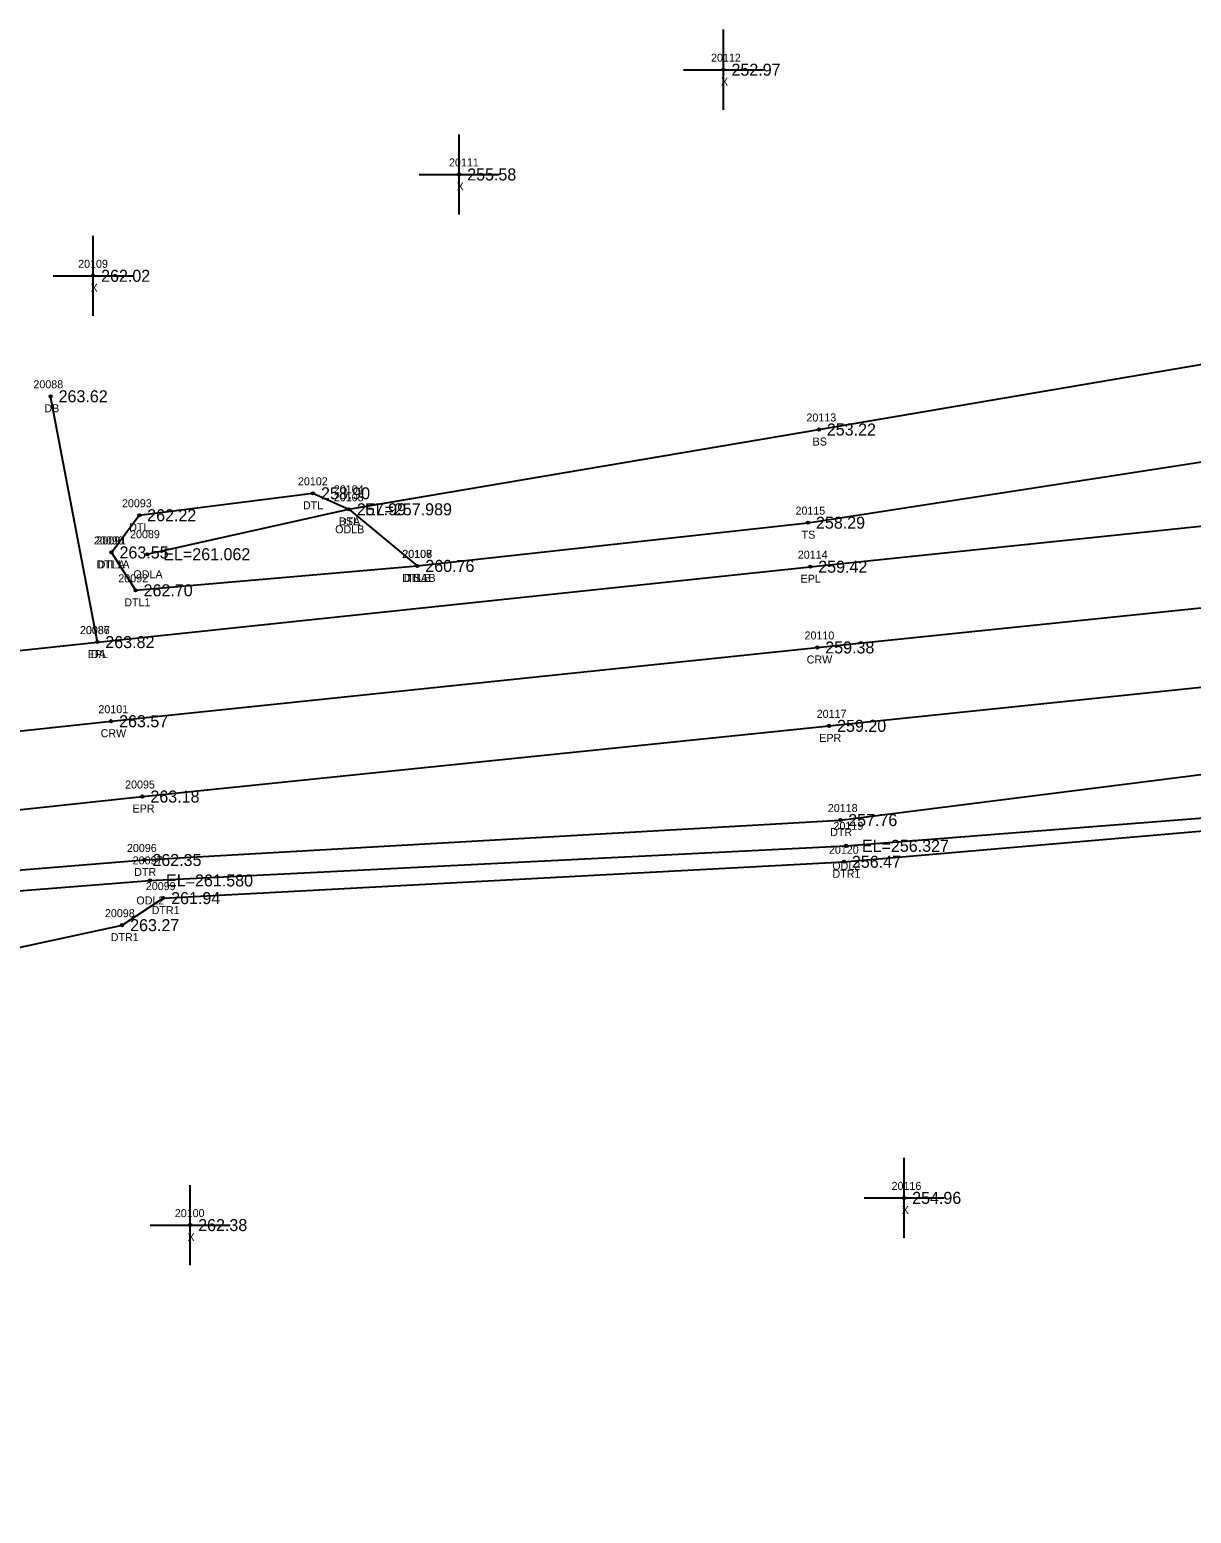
# Model space of a CAD drawing. Extents: x 2275563 to 2277161, y 1075719 to 1076412.
# Drawn here: x 2275956.7 to 2276101.9, y 1075932.2 to 1076117.6 of the extents above; entities that cross this region are included whole.
import ezdxf

# ---------------------------------------------------------------- set-up
doc = ezdxf.new("R2010")
doc.units = 0
for name, color, linetype in [('RD_DTM_BkLn1', 7, 'Continuous'), ('RD_DTM_BkLn2', 7, 'Continuous'), ('RD_DTM_BkLn_txCode', 7, 'Continuous'), ('RD_EX_Driveway', 7, 'Continuous'), ('RD_EX_Driveway_txCode', 7, 'Continuous'), ('RD_EX_H2O', 7, 'Continuous'), ('RD_EX_H2O_txCode', 7, 'Continuous'), ('RD_EX_Misc', 7, 'Continuous'), ('RD_EX_Misc_txCode', 7, 'Continuous'), ('RD_EX_Road', 7, 'Continuous'), ('RD_EX_Road_txCode', 7, 'Continuous'), ('RD_EX_TX_Driveway_ELEV', 7, 'Continuous'), ('RD_EX_TX_H2O_ELEV', 7, 'Continuous'), ('RD_EX_TX_Misc_ELEV', 7, 'Continuous'), ('RD_EX_TX_Road_ELEV', 7, 'Continuous'), ('RD_HC_Survey_ELEV', 7, 'Continuous'), ('RD_HC_Survey_txCode', 7, 'Continuous'), ('RD_SMD_Locator', 7, 'Continuous')]:
    doc.layers.add(name, color=color, linetype=linetype)

msp = doc.modelspace()

# ---------------------------------------------------------------- linework, layer by layer
at = {"layer": 'RD_DTM_BkLn1'}
msp.add_lwpolyline([(2275581.11, 1075960.98), (2275628.56, 1075975.85), (2275676.42, 1075988.42), (2275723.3, 1075998.64), (2275773.11, 1076007.87), (2275820.75, 1076014.85), (2275866.6, 1076020.4), (2275966.91, 1076031.19), (2276055.16, 1076040.4), (2276149.88, 1076050.18), (2276235.38, 1076058.41), (2276319.71, 1076067.21)], dxfattribs=at)
at = {"layer": 'RD_DTM_BkLn2'}
for points in [[(2275996.63, 1076057.66), (2276055.36, 1076067.63), (2276157.86, 1076085.08), (2276161.29, 1076085.91), (2276230.76, 1076096.53), (2276259.06, 1076089.7), (2276286.01, 1076102.67), (2276316.19, 1076099.9), (2276328.57, 1076094.65)], [(2276005.18, 1076050.59), (2276054, 1076055.99), (2276147.58, 1076070.47), (2276233.91, 1076079.18), (2276270.23, 1076080.23), (2276308.93, 1076086.72), (2276316.33, 1076084.42), (2276319.11, 1076080.29)]]:
    msp.add_lwpolyline(points, dxfattribs=at)
at = {"layer": 'RD_EX_Driveway'}
msp.add_line((2275965.19, 1076041.07), (2275959.35, 1076071.78), dxfattribs=at)
at = {"layer": 'RD_EX_H2O'}
msp.add_line((2275971.43, 1076052.05), (2275996.63, 1076057.66), dxfattribs=at)
for points in [[(2275966.96, 1076052.27), (2275970.42, 1076056.92), (2275992.14, 1076059.66), (2275996.63, 1076057.66), (2276005.18, 1076050.59)], [(2275966.96, 1076052.27), (2275969.97, 1076047.54), (2276005.18, 1076050.59)], [(2275584.42, 1075945.55), (2275630.75, 1075959.99), (2275679.72, 1075972.8), (2275727.1, 1075983.01), (2275776.52, 1075992.46), (2275822.09, 1075998.61), (2275868.31, 1076005.5), (2275971.07, 1076013.85), (2276058.03, 1076018.84), (2276110, 1076025.4), (2276114.25, 1076022.31), (2276152.59, 1076021.64), (2276188.46, 1076022.22), (2276200.36, 1076021.35), (2276207.63, 1076015.4), (2276245.53, 1076014.24), (2276263.41, 1076017.81), (2276276.57, 1076007.97), (2276280.95, 1075989.03), (2276329.97, 1075967.39)], [(2275584.66, 1075942.4), (2275631.99, 1075956.6), (2275680.23, 1075970.55), (2275727.34, 1075980.71), (2275776.9, 1075989.93), (2275822.49, 1075996.83), (2275868.2, 1076003.14), (2275971.77, 1076011.3), (2276058.74, 1076015.62), (2276117.31, 1076020.2), (2276152.71, 1076018.31), (2276188.2, 1076020.3), (2276200.59, 1076018.25), (2276207.46, 1076011.88), (2276246.17, 1076010.02), (2276264.15, 1076012.48), (2276274.37, 1076006.56), (2276276.43, 1075986.9), (2276334.04, 1075961.68)], [(2275587.87, 1075932.23), (2275632.3, 1075945.74), (2275680.34, 1075962.3), (2275730.43, 1075971.98), (2275777.84, 1075981.49), (2275823.91, 1075987.34), (2275869.26, 1075992.75), (2275941.88, 1076000), (2275968.29, 1076005.71), (2275973.41, 1076009.09), (2276058.49, 1076013.63), (2276114.54, 1076018.47), (2276125.61, 1076012.99), (2276153.29, 1076014.06), (2276186.69, 1076017.67), (2276196.76, 1076016.05), (2276210.13, 1076008.45), (2276246.2, 1076005.42), (2276264.34, 1076010.6), (2276271.38, 1076006), (2276275.05, 1075983.37), (2276331.39, 1075956.06)]]:
    msp.add_lwpolyline(points, dxfattribs=at)
at = {"layer": 'RD_EX_Misc'}
for p, q in [((2276043.44, 1076107.58), (2276043.44, 1076117.58)), ((2276038.44, 1076112.58), (2276048.44, 1076112.58)), ((2276010.41, 1076094.49), (2276010.41, 1076104.49)), ((2276005.41, 1076099.49), (2276015.41, 1076099.49)), ((2275964.66, 1076081.83), (2275964.66, 1076091.83)), ((2275959.66, 1076086.83), (2275969.66, 1076086.83)), ((2276066.02, 1075966.64), (2276066.02, 1075976.64)), ((2275976.79, 1075963.24), (2275976.79, 1075973.24)), ((2276061.02, 1075971.64), (2276071.02, 1075971.64)), ((2275971.79, 1075968.24), (2275981.79, 1075968.24))]:
    msp.add_line(p, q, dxfattribs=at)
at = {"layer": 'RD_EX_Road'}
for points in [[(2275577.73, 1075970.55), (2275625.95, 1075985.49), (2275674.01, 1075998.04), (2275722.5, 1076008.98), (2275771.65, 1076017.82), (2275820.48, 1076025.1), (2275865.7, 1076030.61), (2275949.17, 1076039.36), (2275965.19, 1076041.07), (2276054.28, 1076050.49), (2276149.42, 1076060.39), (2276235.13, 1076068.68), (2276318.87, 1076076.96)], [(2275583.24, 1075951.04), (2275629.66, 1075965.93), (2275678.06, 1075978.68), (2275725.56, 1075989.06), (2275775.66, 1075998.23), (2275820.79, 1076005.15), (2275867.87, 1076010.76), (2275970.82, 1076021.78), (2276056.64, 1076030.61), (2276150.8, 1076040.39), (2276237.04, 1076048.76), (2276320.71, 1076057.95)]]:
    msp.add_lwpolyline(points, dxfattribs=at)
at = {"layer": 'RD_SMD_Locator'}
for centre in [(2276043.44, 1076112.58), (2276010.41, 1076099.49), (2275964.66, 1076086.83), (2275959.35, 1076071.78), (2276055.36, 1076067.63), (2275992.14, 1076059.66), (2275970.42, 1076056.92), (2275996.63, 1076057.66), (2275996.63, 1076057.66), (2275996.63, 1076057.66), (2276054, 1076055.99), (2275966.96, 1076052.27), (2275966.96, 1076052.27), (2275971.43, 1076052.05), (2276005.18, 1076050.59), (2276005.18, 1076050.59), (2276005.18, 1076050.59), (2276054.28, 1076050.49), (2275969.97, 1076047.54), (2275965.19, 1076041.07), (2275965.19, 1076041.07), (2276055.16, 1076040.4), (2275966.91, 1076031.19), (2276056.64, 1076030.61), (2275970.82, 1076021.78), (2276058.03, 1076018.84), (2276058.74, 1076015.62), (2275971.07, 1076013.85), (2276058.49, 1076013.63), (2275971.77, 1076011.3), (2275973.41, 1076009.09), (2275968.29, 1076005.71), (2276066.02, 1075971.64), (2275976.79, 1075968.24)]:
    msp.add_circle(centre, 0.15, dxfattribs=at)

# ---------------------------------------------------------------- texts
at = {"layer": 'RD_DTM_BkLn_txCode'}
for s, p in [('20113', (2276053.81, 1076068.63)), ('BS', (2276054.58, 1076065.63)), ('20105', (2275994.75, 1076058.66)), ('BSA', (2275995.36, 1076055.66)), ('20115', (2276052.44, 1076056.99)), ('TS', (2276053.2, 1076053.99)), ('20108', (2276003.31, 1076051.59)), ('TSA', (2276003.9, 1076048.59))]:
    msp.add_text(s, height=1, dxfattribs=at).set_placement(p)
at = {"layer": 'RD_EX_Driveway_txCode'}
for s, p in [('20088', (2275957.2, 1076072.78)), ('DB', (2275958.57, 1076069.78)), ('20087', (2275963.03, 1076042.07)), ('DA', (2275964.39, 1076039.07))]:
    msp.add_text(s, height=1, dxfattribs=at).set_placement(p)
at = {"layer": 'RD_EX_H2O_txCode'}
for s, p in [('20102', (2275990.26, 1076060.66)), ('20104', (2275994.75, 1076059.66)), ('20093', (2275968.27, 1076057.92)), ('DTL', (2275990.89, 1076057.66)), ('20103', (2275994.75, 1076058.66)), ('DTL', (2275995.38, 1076055.66)), ('DTL', (2275969.18, 1076054.92)), ('20089', (2275969.28, 1076054.05)), ('ODLB', (2275994.91, 1076054.66)), ('20090', (2275964.76, 1076053.27)), ('20091', (2275965.08, 1076053.27)), ('20106', (2276003.29, 1076051.59)), ('20107', (2276003.31, 1076051.59)), ('DTL1A', (2275965.06, 1076050.27)), ('DTLA', (2275965.23, 1076050.27)), ('20092', (2275967.81, 1076048.54)), ('ODLA', (2275969.7, 1076049.05)), ('DTL1B', (2276003.3, 1076048.59)), ('DTLB', (2276003.47, 1076048.59)), ('DTL1', (2275968.56, 1076045.54)), ('20118', (2276056.48, 1076019.84)), ('DTR', (2276056.77, 1076016.84)), ('20119', (2276057.19, 1076017.62)), ('20096', (2275968.89, 1076014.85)), ('20120', (2276056.62, 1076014.63)), ('20097', (2275969.61, 1076013.3)), ('ODL2', (2276057.04, 1076012.62)), ('DTR', (2275969.8, 1076011.85)), ('DTR1', (2276057.06, 1076011.63)), ('20099', (2275971.25, 1076010.09)), ('ODL2', (2275970.07, 1076008.3)), ('DTR1', (2275971.98, 1076007.09)), ('20098', (2275966.14, 1076006.71)), ('DTR1', (2275966.86, 1076003.71))]:
    msp.add_text(s, height=1, dxfattribs=at).set_placement(p)
at = {"layer": 'RD_EX_Misc_txCode'}
for s, p in [('20112', (2276041.89, 1076113.58)), ('X', (2276043.13, 1076110.58)), ('20111', (2276009.14, 1076100.49)), ('X', (2276010.1, 1076097.49)), ('20109', (2275962.79, 1076087.83)), ('X', (2275964.35, 1076084.83)), ('20116', (2276064.45, 1075972.64)), ('20100', (2275974.87, 1075969.24)), ('X', (2276065.71, 1075969.64)), ('X', (2275976.47, 1075966.24))]:
    msp.add_text(s, height=1, dxfattribs=at).set_placement(p)
at = {"layer": 'RD_EX_Road_txCode'}
for s, p in [('20114', (2276052.73, 1076051.49)), ('EPL', (2276053.08, 1076048.49)), ('20086', (2275963.01, 1076042.07)), ('EPL', (2275963.98, 1076039.07)), ('20117', (2276055.09, 1076031.61)), ('EPR', (2276055.41, 1076028.61)), ('20095', (2275968.66, 1076022.78)), ('EPR', (2275969.59, 1076019.78))]:
    msp.add_text(s, height=1, dxfattribs=at).set_placement(p)
at = {"layer": 'RD_EX_TX_Driveway_ELEV'}
for s, p in [('263.62', (2275960.35, 1076071.03)), ('263.82', (2275966.19, 1076040.32))]:
    msp.add_text(s, height=1.5, dxfattribs=at).set_placement(p)
at = {"layer": 'RD_EX_TX_H2O_ELEV'}
for s, p in [('258.90', (2275993.14, 1076058.91)), ('257.99', (2275997.63, 1076056.91)), ('EL=257.989', (2275998.63, 1076056.91)), ('262.22', (2275971.42, 1076056.17)), ('263.55', (2275967.96, 1076051.52)), ('263.55', (2275967.96, 1076051.52)), ('EL=261.062', (2275973.43, 1076051.3)), ('260.76', (2276006.18, 1076049.84)), ('260.76', (2276006.18, 1076049.84)), ('262.70', (2275970.97, 1076046.79)), ('257.76', (2276059.03, 1076018.09)), ('EL=256.327', (2276060.74, 1076014.87)), ('262.35', (2275972.07, 1076013.1)), ('256.47', (2276059.49, 1076012.88)), ('EL=261.580', (2275973.77, 1076010.55)), ('261.94', (2275974.41, 1076008.34)), ('263.27', (2275969.29, 1076004.96))]:
    msp.add_text(s, height=1.5, dxfattribs=at).set_placement(p)
at = {"layer": 'RD_EX_TX_Misc_ELEV'}
for s, p in [('252.97', (2276044.44, 1076111.83)), ('255.58', (2276011.41, 1076098.74)), ('262.02', (2275965.66, 1076086.08)), ('253.22', (2276056.36, 1076066.88)), ('257.99', (2275997.63, 1076056.91)), ('258.29', (2276055, 1076055.24)), ('260.76', (2276006.18, 1076049.84)), ('254.96', (2276067.02, 1075970.89)), ('262.38', (2275977.79, 1075967.49))]:
    msp.add_text(s, height=1.5, dxfattribs=at).set_placement(p)
at = {"layer": 'RD_EX_TX_Road_ELEV'}
for s, p in [('259.42', (2276055.28, 1076049.74)), ('263.82', (2275966.19, 1076040.32)), ('259.20', (2276057.64, 1076029.86)), ('263.18', (2275971.82, 1076021.03))]:
    msp.add_text(s, height=1.5, dxfattribs=at).set_placement(p)
at = {"layer": 'RD_HC_Survey_ELEV'}
for s, p in [('259.38', (2276056.16, 1076039.65)), ('263.57', (2275967.91, 1076030.44))]:
    msp.add_text(s, height=1.5, dxfattribs=at).set_placement(p)
at = {"layer": 'RD_HC_Survey_txCode'}
for s, p in [('20110', (2276053.57, 1076041.4)), ('CRW', (2276053.84, 1076038.4)), ('20101', (2275965.32, 1076032.19)), ('CRW', (2275965.6, 1076029.19))]:
    msp.add_text(s, height=1, dxfattribs=at).set_placement(p)

doc.saveas('drawing.dxf')
